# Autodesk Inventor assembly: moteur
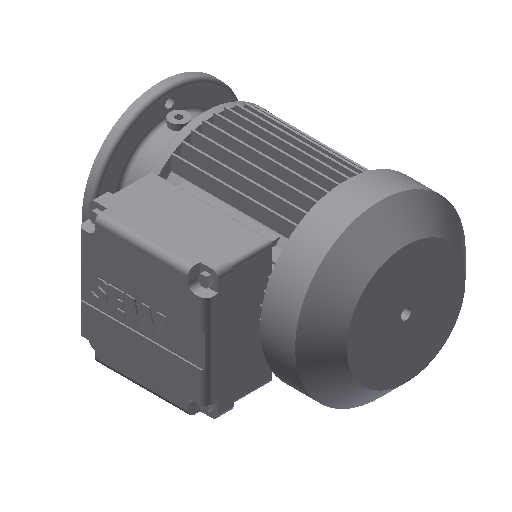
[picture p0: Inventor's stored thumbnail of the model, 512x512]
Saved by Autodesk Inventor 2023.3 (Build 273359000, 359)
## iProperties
Created: 2012-12
Part Number: moteur
Document SubType Name: Assembly
Designer: jost thierry
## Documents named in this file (10)
- E:\Dossier technique\Reducteur\TD02-Reducteur S37\TD02-Reducteur-Ressources\TD02-Reduct-3D\moteur.iam
- E:\Dossier technique\Reducteur\TD02-Reducteur S37\TD02-Reducteur-Ressources\TD02-Reduct-3D\PRODUCT_NAME_14.ipt
- E:\Dossier technique\Reducteur\TD02-Reducteur S37\TD02-Reducteur-Ressources\TD02-Reduct-3D\PRODUCT_NAME_15.ipt
- E:\Dossier technique\Reducteur\TD02-Reducteur S37\TD02-Reducteur-Ressources\TD02-Reduct-3D\PRODUCT_NAME_16.ipt
- E:\Dossier technique\Reducteur\TD02-Reducteur S37\TD02-Reducteur-Ressources\TD02-Reduct-3D\PRODUCT_NAME_17.ipt
- E:\Dossier technique\Reducteur\TD02-Reducteur S37\TD02-Reducteur-Ressources\TD02-Reduct-3D\PRODUCT_NAME_21.ipt
- E:\Dossier technique\Reducteur\TD02-Reducteur S37\TD02-Reducteur-Ressources\TD02-Reduct-3D\PRODUCT_NAME_22.ipt
- E:\Dossier technique\Reducteur\TD02-Reducteur S37\TD02-Reducteur-Ressources\TD02-Reduct-3D\PRODUCT_NAME_23.ipt
- E:\Dossier technique\Reducteur\TD02-Reducteur S37\TD02-Reducteur-Ressources\TD02-Reduct-3D\PRODUCT_NAME_25.ipt
- E:\Dossier technique\Reducteur\TD02-Reducteur S37\TD02-Reducteur-Ressources\TD02-Reduct-3D\PRODUCT_NAME_26.ipt
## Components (9 placed, 9 different names)
1. PRODUCT_NAME_14:1
2. PRODUCT_NAME_15:1
3. PRODUCT_NAME_16:1
4. PRODUCT_NAME_17:1
5. PRODUCT_NAME_21:1
6. PRODUCT_NAME_22:1
7. PRODUCT_NAME_23:1
8. PRODUCT_NAME_25:1
9. PRODUCT_NAME_26:1
